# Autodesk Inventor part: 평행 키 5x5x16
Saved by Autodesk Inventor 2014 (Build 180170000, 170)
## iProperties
Created: 2026-07
Part Number: 평행 키 5x5x16
Material: 일반
Document SubType Name: Modeling
Designer: dg
Density: 1 g/cm^3
Appearance: 기본값
Author: dg
Author: jhkim
Description: 키 및 해당 키홈
Creation Date: 2026-07-02
Sending System: Autodesk Inventor 2027
Preprocessor: ST-DEVELOPER v20.1
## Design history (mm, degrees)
node "평행 키 5x5x161"
body "Solid1"
node "기준1"
